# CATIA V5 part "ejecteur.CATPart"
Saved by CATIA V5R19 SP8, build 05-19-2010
Part number: ejecteur
Bounding box of the stored display mesh (mm): x -5.309 to 1.098, y -2.93 to 12.71, z -5 to 4.5
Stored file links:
  E:\Catia parts\GLOCK\Ensemble culasse\ejecteur.CATPart
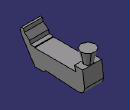
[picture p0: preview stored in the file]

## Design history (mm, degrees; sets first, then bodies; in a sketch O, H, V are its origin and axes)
Body1 (main body)
  Solid1: solid without history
